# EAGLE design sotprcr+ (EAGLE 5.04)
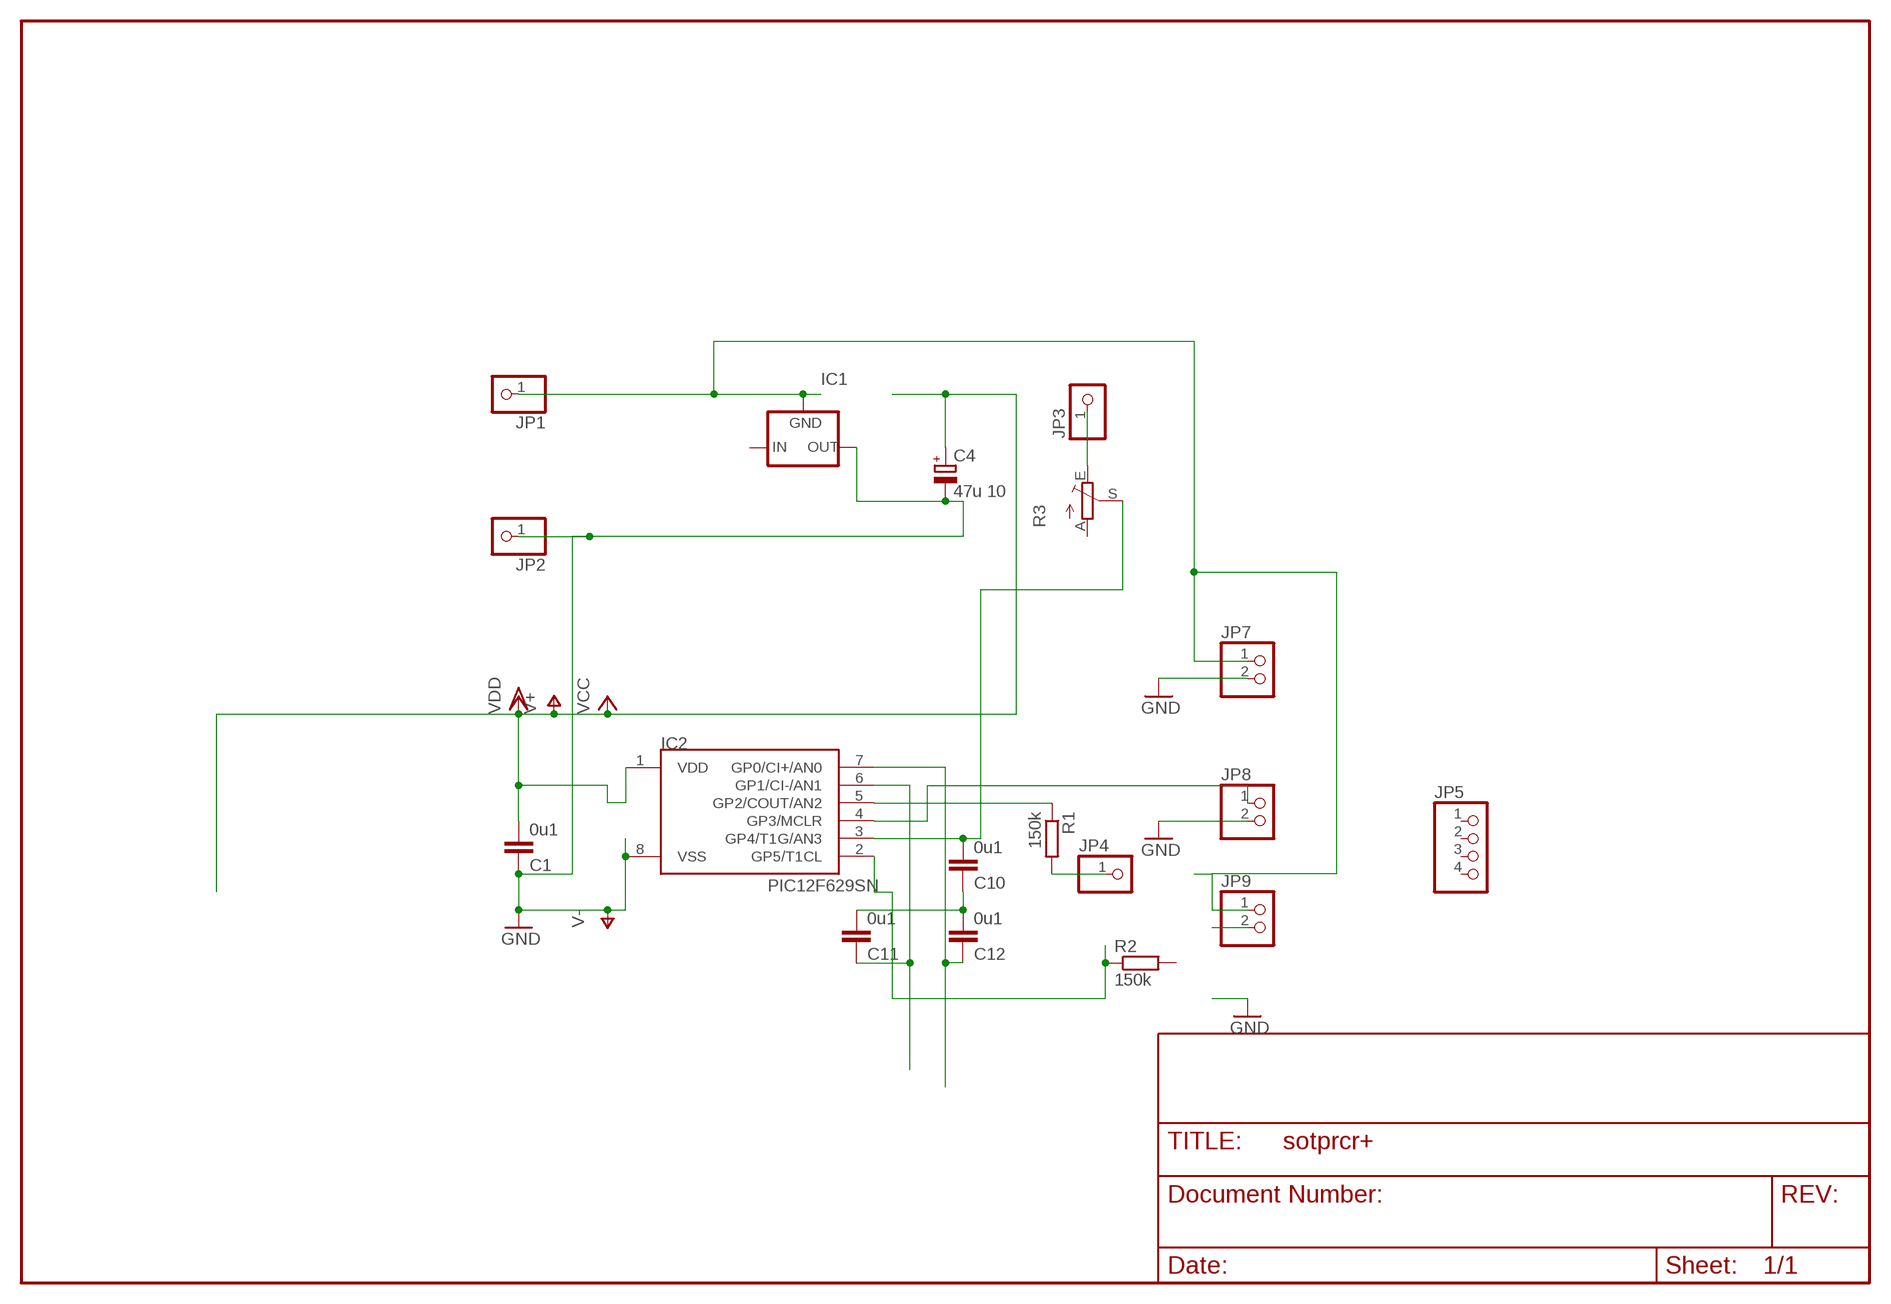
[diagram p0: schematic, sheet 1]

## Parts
C1  0u1  C-EUC1206  [C1206]
C4  47u 10  CPOL-EUE2.5-6  [E2,5-6]
C10  0u1  C-EUC1206  [C1206]
C11  0u1  C-EUC1206  [C1206]
C12  0u1  C-EUC1206  [C1206]
IC1  79LXX  [79LXX]
IC2  PIC12F629SN  [SO-08]
JP1  PINHD-1X1  [1X01]
JP2  PINHD-1X1  [1X01]
JP3  PINHD-1X1  [1X01]
JP4  PINHD-1X1  [1X01]
JP5  PINHD-1X4  [1X04]
JP7  PINHD-1X2  [1X02]
JP8  PINHD-1X2  [1X02]
JP9  PINHD-1X2  [1X02]
R1  150k  R-EU_R0805  [R0805]
R2  150k  R-EU_R1206  [R1206]
R3  TRIM_EU-CA6V  [CA6V]

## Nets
GND: C1.1 C4.- IC1.OUT IC2.8(VSS) JP2.1 JP7.2 JP8.2 ; supply symbol labelled V-
N$1: JP3.1 R3.E
N$2: JP4.1 R1.2
N$3: IC2.4(GP3/MCLR) JP8.1
N$4: C10.1 C11.2 C12.2
N$5: IC2.5(GP2/COUT/AN2) R1.1
N$8: IC2.2(GP5/T1CL) R2.1
N$10: JP9.2
N$12: C10.2 IC2.3(GP4/T1G/AN3) R3.S
N$13: C12.1 IC2.7(GP0/CI+/AN0)
N$15: C11.1 IC2.6(GP1/CI-/AN1)
N$20: IC1.GND JP1.1 JP7.1 JP9.1
V+: C1.2 C4.+ IC2.1(VDD) ; supply symbol labelled VCC, VDD
Unconnected: IC1.IN JP5.1 JP5.2 JP5.3 JP5.4 R2.2 R3.A

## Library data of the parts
C1 C10-C12 = rcl:C-EU: CAPACITOR, European symbol
C4 = rcl:CPOL-EU: POLARIZED CAPACITOR, European symbol
IC1 = v-reg:79LXX: VOLTAGE REGULATOR
IC2 = microchip-3:PIC12F6*: uPC nW 1k Program Flash memory 2x Timer Comparator 10b A/D converter/ 4xIN
JP1-JP4 = pinhead:PINHD-1X1: PIN HEADER
JP5 = pinhead(2):PINHD-1X4: PIN HEADER
JP7-JP9 = pinhead:PINHD-1X2: PIN HEADER
R1 R2 = rcl:R-EU_: RESISTOR, European symbol
R3 = pot:TRIM_EU-: POTENTIOMETER

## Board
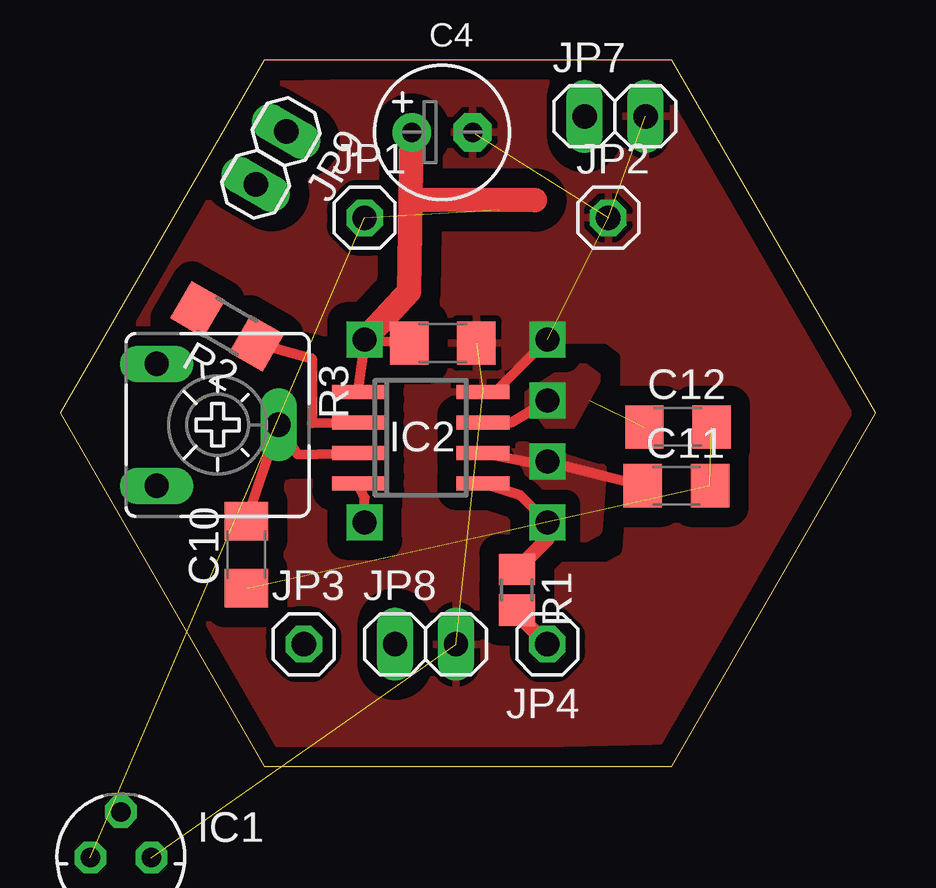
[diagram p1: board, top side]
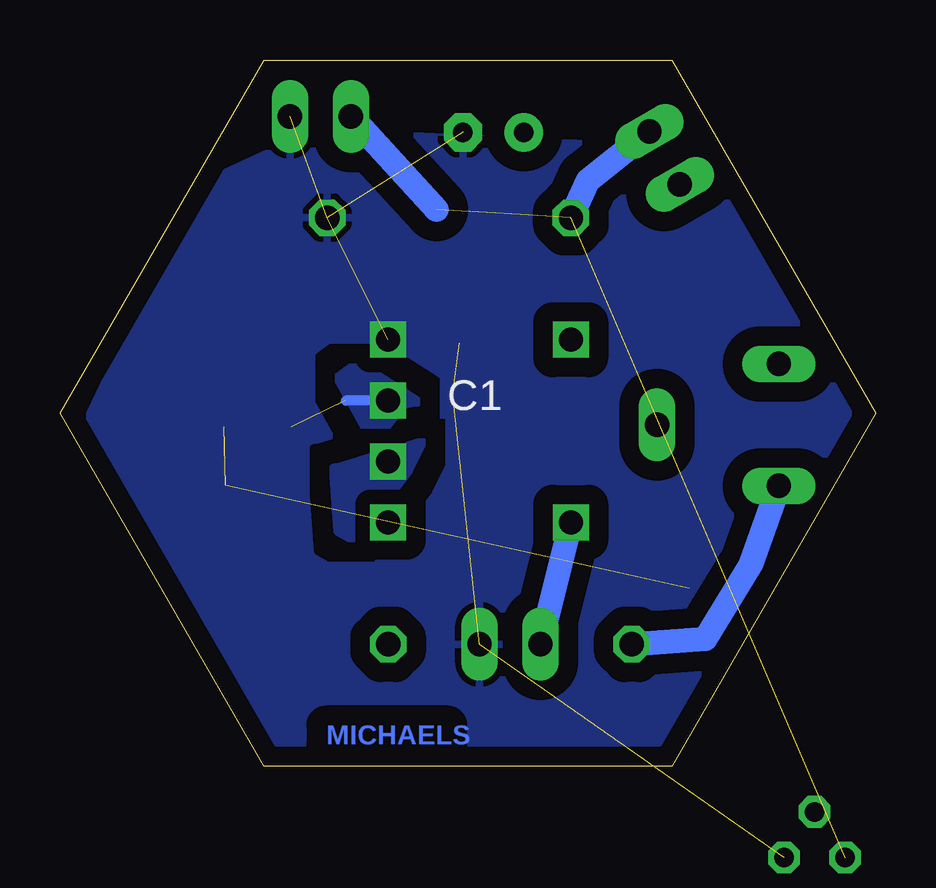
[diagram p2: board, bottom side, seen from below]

Size 34 x 29.44 mm. Coordinates in mm from the lower left corner, seen from the top.
Outline: 8.5,0 25.5,0 34,14.72 25.5,29.44 8.5,29.44 0,14.72 8.5,0
Copper layers (1*16): Top 0.035mm / dielectric 1.5mm / Bottom 0.035mm
Design rules "default *": minimum track width 10mil, minimum drill 24mil, track to track 8mil, track to pad 8mil, pad to pad 8mil, via to via 8mil, smd to smd 8mil, copper to edge 10mil, drill to drill 8mil, minimum pad ring 10mil, minimum via ring 8mil, stop-mask expansion 4mil, vias tented up to drill 0mil, thermal gap 10mil

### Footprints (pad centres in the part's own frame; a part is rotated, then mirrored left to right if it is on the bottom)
C1206 = smd 1.6 x 1.8: 1 -1.4,0; 2 1.4,0
E2,5-6 = drill 0.813 pad 1.6 round: + -1.27,0 | drill 0.813 pad 1.6 octagon: - 1.27,0
79LXX = drill 0.813 octagon: GND -1.27,0; IN 0,1.905; OUT 1.27,0
SO-08 = smd 0.6 x 2.2: 1 -1.905,-2.6; 2 -0.635,-2.6; 3 0.635,-2.6; 4 1.905,-2.6; 5 1.905,2.6; 6 0.635,2.6; 7 -0.635,2.6; 8 -1.905,2.6
1X01 = drill 1.016 octagon: 1 0,0
1X04 = drill 1.016 square: 1 -3.81,0 | drill 1.016 octagon: 2 -1.27,0; 3 1.27,0; 4 3.81,0
1X02 = drill 1.016 long: 1 -1.27,0; 2 1.27,0
R0805 = smd 1.3 x 1.5: 1 -0.85,0; 2 0.85,0
R1206 = smd 1.6 x 1.803: 1 -1.422,0; 2 1.422,0
CA6V = drill 1.016 long: A -2.54,-2.54; E 2.54,-2.54; S 0,2.54

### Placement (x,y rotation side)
C1  15.96,17.64 180 top
C4  15.93,26.42 0 top
C10  7.77,8.81 90 top
C11  25.7,11.69 0 top
C12  25.76,14.14 0 top
IC1  2.54,-3.81 0 top
IC2  15.04,13.69 270 top
JP1  12.7,22.86 0 top
JP2  22.86,22.86 0 top
JP3  10.16,5.08 0 top
JP4  20.32,5.08 180 top
JP5  not placed on the board
JP7  23.14,27.09 0 top
JP8  15.24,5.08 0 top
JP9  8.79,25.36 240 top
R1  19.05,7.35 270 top
R2  6.97,18.34 150 top
R3  6.57,14.23 270 top

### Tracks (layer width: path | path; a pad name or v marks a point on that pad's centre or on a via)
GND  (via drill 1)  (6 unrouted)
  Top 0.406: IC2.8 18.24,15.7 v20.32,17.78
  Bottom 0.406: v20.32,17.78 20.18,17.78
  pour Top (isolate 0.813, rank 4): 25.05,28.74 33.52,14.83 25.59,1.05 7.24,0.65 -0.28,14.57 9.11,28.44
  pour Bottom (isolate 0.813, rank 4): 25.09,0.65 6.94,0.85 -0.63,14.71 7.44,25.75 23.4,26.48 28.25,24.24 33.14,13.91
N$1
  Bottom 1.016: R3.E 5.2,8.4 7.1,5.3 JP3.1
N$2
  Top 0.61: R1.2 19.05,6.35 JP4.1
N$3  (via drill 1)
  Top 0.406: IC2.4 12.7,11.19 v12.7,10.16
  Bottom 1.016: JP8.1 v12.7,10.16
N$4  (2 unrouted)
N$5  (via drill 1)
  Top 0.406: IC2.5 19.19,11.29 v20.32,10.16
  Top 0.61: v20.32,10.16 20.32,9.47 R1.1
N$8
  Top 0.406: R2.1 10.5,17 10.5,14.3 IC2.2
N$12
  Top 0.406: IC2.3 9.9,13 R3.S C10.2
N$13  (via drill 1)  (1 unrouted)
  Top 0.406: IC2.7 18.81,14.33 v20.32,15.24
  Bottom 0.406: v20.32,15.24 22.08,15.24
  pour Top (isolate 0.61): 19.7,15.1 20.9,13.5 22.4,16.2 21.6,16.8 19.1,15.2
  pour Bottom (isolate 0.61): 19.7,15.1 20.9,13.5 22.4,16.2 21.6,16.8 19.1,15.2
N$15  (via drill 1)
  Top 0.406: IC2.6 20.18,12.56 v20.32,12.7 C11.1
  pour Top (isolate 0.61, rank 2): 18.9,13.5 22.4,12.4 22.6,12.4 22.4,9.8 21.7,9.4 19.5,12.3
  pour Bottom (isolate 0.61, rank 2): 18.9,13.5 22.4,12.4 22.6,12.4 22.4,9.8 21.7,9.4 19.5,12.3
N$20  (2 unrouted)
  Bottom 1.016: 18.3,23.2 JP7.1 | JP9.1 12,24.4 JP1.1
V+  (via drill 1)
  Top 0.406: IC2.1 12.7,17.54 v12.7,17.78 C1.2
  Top 1.016: v12.7,17.78 14.56,19.78 14.62,23.61 | 14.62,23.61 C4.+ | 14.62,23.61 19.8,23.6

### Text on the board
Bottom: MICHAELS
